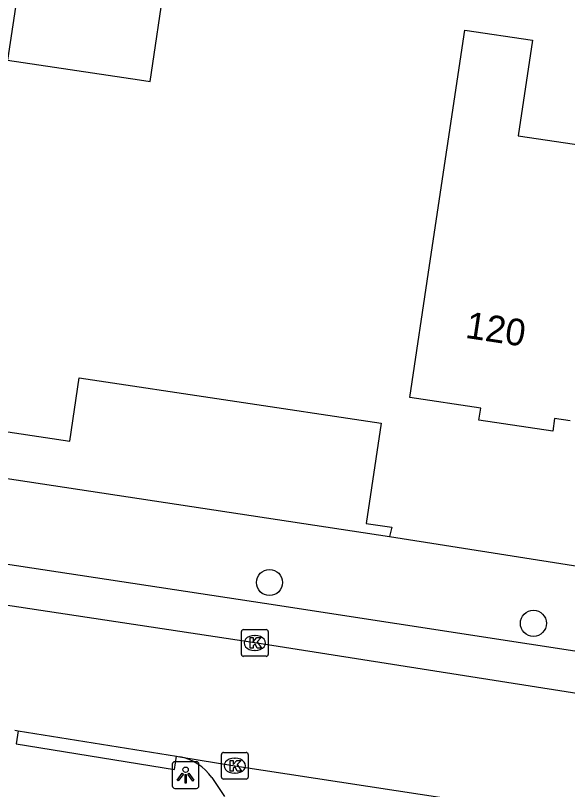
# Model space of a CAD drawing. Extents: x 161486 to 162249, y 379484 to 380829.
# Drawn here: x 161697.24 to 161717.93, y 380576.04 to 380605.05 of the extents above; entities that cross this region are included whole.
import ezdxf

# ---------------------------------------------------------------- set-up
doc = ezdxf.new("R2010")
doc.units = 0
for name, color, linetype in [('IMGEO_Boom', 7, 'Continuous'), ('IMGEO_Kolk', 7, 'Continuous'), ('IMGEO_Lichtpunt', 7, 'Continuous'), ('IMGEO_Pand', 7, 'Continuous'), ('IMGEO_Pand_nummerreeks', 7, 'Continuous'), ('IMGEO_Rijbaan_lokaal_open', 7, 'Continuous'), ('IMGEO_Voetpad_open', 7, 'Continuous')]:
    doc.layers.add(name, color=color, linetype=linetype)

msp = doc.modelspace()

# ---------------------------------------------------------------- linework, layer by layer
at = {"layer": 'IMGEO_Boom'}
for centre in [(161706.758, 380583.801), (161716.651, 380582.272)]:
    msp.add_circle(centre, 0.489, dxfattribs=at)
at = {"layer": 'IMGEO_Kolk'}
for p, q in [((161705.782, 380582.035), (161706.634, 380582.035)), ((161705.707, 380581.109), (161705.707, 380581.961)), ((161706.195, 380581.815), (161706.22, 380581.815)), ((161706.708, 380581.961), (161706.708, 380581.109)), ((161706.218, 380581.255), (161706.193, 380581.255)), ((161706.634, 380581.035), (161705.782, 380581.035)), ((161704.957, 380576.508), (161704.957, 380577.36)), ((161705.032, 380577.434), (161705.884, 380577.434)), ((161705.958, 380577.36), (161705.958, 380576.508)), ((161705.445, 380577.214), (161705.47, 380577.214)), ((161705.468, 380576.654), (161705.443, 380576.654)), ((161705.884, 380576.434), (161705.032, 380576.434))]:
    msp.add_line(p, q, dxfattribs=at)
for points in [[(161705.782, 380582.035), (161706.634, 380582.035)], [(161705.707, 380581.109), (161705.707, 380581.961)], [(161706.028, 380581.735), (161706.151, 380581.735), (161706.151, 380581.584), (161706.281, 380581.735), (161706.445, 380581.735), (161706.299, 380581.584), (161706.452, 380581.335), (161706.3, 380581.335), (161706.215, 380581.499), (161706.151, 380581.432), (161706.151, 380581.335), (161706.028, 380581.335), (161706.028, 380581.735)], [(161706.708, 380581.961), (161706.708, 380581.109)], [(161706.634, 380581.035), (161705.782, 380581.035)], [(161704.957, 380576.508), (161704.957, 380577.36)], [(161705.032, 380577.434), (161705.884, 380577.434)], [(161705.958, 380577.36), (161705.958, 380576.508)], [(161705.278, 380577.134), (161705.401, 380577.134), (161705.401, 380576.983), (161705.531, 380577.134), (161705.695, 380577.134), (161705.549, 380576.983), (161705.702, 380576.734), (161705.55, 380576.734), (161705.465, 380576.898), (161705.401, 380576.831), (161705.401, 380576.734), (161705.278, 380576.734), (161705.278, 380577.134)], [(161705.884, 380576.434), (161705.032, 380576.434)]]:
    msp.add_lwpolyline(points, dxfattribs=at)
for centre, start, end in [((161705.784, 380581.959), 91.552, 178.448), ((161705.784, 380581.959), 91.552, 178.448), ((161706.632, 380581.959), 1.552, 88.448), ((161706.632, 380581.959), 1.552, 88.448), ((161705.784, 380581.111), 181.552, 268.448), ((161705.784, 380581.111), 181.552, 268.448), ((161706.632, 380581.111), 271.552, 358.448), ((161706.632, 380581.111), 271.552, 358.448), ((161705.034, 380577.358), 91.552, 178.448), ((161705.034, 380577.358), 91.552, 178.448), ((161705.882, 380577.358), 1.552, 88.448), ((161705.882, 380577.358), 1.552, 88.448), ((161705.034, 380576.51), 181.552, 268.448), ((161705.034, 380576.51), 181.552, 268.448), ((161705.882, 380576.51), 271.552, 358.448), ((161705.882, 380576.51), 271.552, 358.448)]:
    msp.add_arc(centre, 0.0765, start, end, dxfattribs=at)
for centre, major_axis, ratio, start_param, end_param in [((161706.194, 380581.535), (-0.387, 0.002), 0.722429, 4.712389, 7.853982), ((161706.219, 380581.535), (-0.39, 0.002), 0.717154, 1.570796, 4.712389), ((161705.444, 380576.934), (-0.387, 0.002), 0.722429, 4.712389, 7.853982), ((161705.469, 380576.934), (-0.39, 0.002), 0.717154, 1.570796, 4.712389)]:
    msp.add_ellipse(centre, major_axis=major_axis, ratio=ratio, start_param=start_param, end_param=end_param, dxfattribs=at)
at = {"layer": 'IMGEO_Lichtpunt'}
for p, q in [((161704.017, 380577.084), (161703.209, 380577.084)), ((161704.017, 380577.084), (161703.209, 380577.084)), ((161703.115, 380576.989), (161703.115, 380576.182)), ((161703.115, 380576.989), (161703.115, 380576.182)), ((161704.111, 380576.182), (161704.111, 380576.989)), ((161704.111, 380576.182), (161704.111, 380576.989)), ((161703.209, 380576.088), (161704.017, 380576.088)), ((161703.209, 380576.088), (161704.017, 380576.088))]:
    msp.add_line(p, q, dxfattribs=at)
for points in [[(161703.489, 380576.653), (161703.528, 380576.625), (161703.34, 380576.363), (161703.302, 380576.39), (161703.489, 380576.653)], [(161703.591, 380576.605), (161703.638, 380576.605), (161703.638, 380576.283), (161703.591, 380576.283), (161703.591, 380576.605)], [(161703.701, 380576.625), (161703.739, 380576.652), (161703.926, 380576.39), (161703.887, 380576.362), (161703.701, 380576.625)]]:
    msp.add_lwpolyline(points, dxfattribs=at)
msp.add_circle((161703.614, 380576.787), 0.0994, dxfattribs=at)
for centre, start, end in [((161703.209, 380576.989), 90, 180), ((161703.209, 380576.989), 90, 180), ((161704.017, 380576.989), 0, 90), ((161704.017, 380576.989), 0, 90), ((161703.209, 380576.182), 180, 270), ((161703.209, 380576.182), 180, 270), ((161704.017, 380576.182), 270, 0), ((161704.017, 380576.182), 270, 360)]:
    msp.add_arc(centre, 0.0946, start, end, dxfattribs=at)
at = {"layer": 'IMGEO_Pand'}
for points in [[(161688.336, 380617.311), (161687.614, 380612.476), (161686.663, 380612.618), (161686.281, 380610.06), (161687.125, 380609.934), (161687.013, 380609.186), (161697.574, 380607.607), (161696.942, 380603.375), (161701.887, 380602.635), (161702.283, 380602.576), (161702.852, 380606.383), (161701.954, 380606.517), (161703.216, 380614.962)], [(161718.025, 380589.859), (161717.444, 380589.946), (161717.374, 380589.474), (161714.61, 380589.887), (161714.678, 380590.34), (161712.018, 380590.738), (161712.757, 380595.684), (161714.076, 380604.503), (161716.615, 380604.124), (161716.079, 380600.544), (161719.544, 380600.026)], [(161679.209, 380599.887), (161687.051, 380598.715), (161687.633, 380602.612), (161692.578, 380601.873), (161693.597, 380601.721), (161691.87, 380590.21), (161699.267, 380589.1), (161699.623, 380591.473), (161710.946, 380589.774), (161710.382, 380586.016), (161711.341, 380585.872), (161711.262, 380585.528)], [(161682.27, 380589.92), (161711.262, 380585.528)]]:
    msp.add_lwpolyline(points, dxfattribs=at)
at = {"layer": 'IMGEO_Rijbaan_lokaal_open'}
for points in [[(161748.16, 380575.062), (161745.481, 380575.457), (161727.091, 380578.257), (161706.209, 380581.535), (161684.371, 380584.84), (161680.794, 380585.397)], [(161697.21, 380578.268), (161697.341, 380578.247)], [(161697.341, 380578.247), (161703.276, 380577.288)], [(161703.276, 380577.288), (161703.396, 380577.269)], [(161703.396, 380577.269), (161705.458, 380576.935), (161723.434, 380574.186), (161743.383, 380571.123), (161747.528, 380570.507)]]:
    msp.add_lwpolyline(points, dxfattribs=at)
at = {"layer": 'IMGEO_Voetpad_open'}
for points in [[(161751.383, 380576.136), (161706.575, 380583.016), (161683.607, 380586.497)], [(161711.262, 380585.528), (161724.808, 380583.386), (161754.33, 380578.833), (161755.449, 380578.66)], [(161697.341, 380578.247), (161697.261, 380577.755), (161703.196, 380576.793), (161703.276, 380577.288)], [(161704.594, 380576.489), (161705.068, 380575.783)]]:
    msp.add_lwpolyline(points, dxfattribs=at)
msp.add_arc((161703.044, 380575.419), 1.883, 34.6294, 79.2355, dxfattribs=at)

# ---------------------------------------------------------------- texts
at = {"layer": 'IMGEO_Pand_nummerreeks'}
msp.add_text('120', height=1, rotation=351.3577, dxfattribs=at).set_placement((161714.067, 380592.975))

doc.saveas('drawing.dxf')
